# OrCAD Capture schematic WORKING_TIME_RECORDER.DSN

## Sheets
1 DOOR: size A; title: Door controler Eletronic Schematic; rev: DRC; note: 4
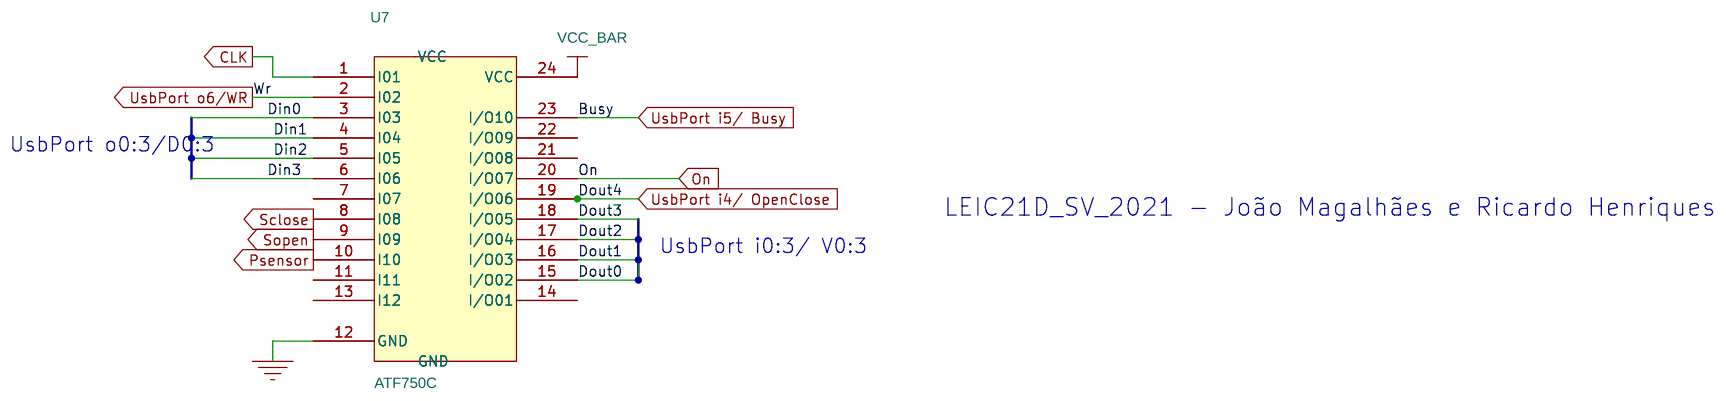
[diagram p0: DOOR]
2 LCD: size A; title: LCD Eletronic Schematic; rev: LCD; note: 3
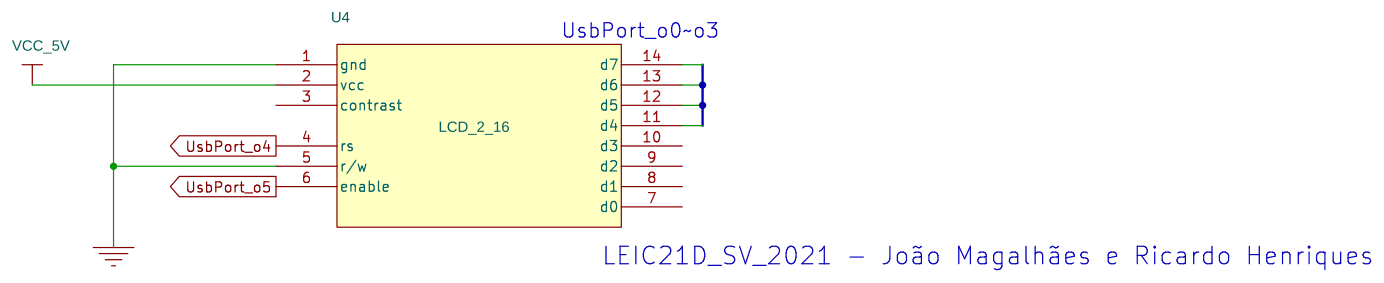
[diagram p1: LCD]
3 KeyTransmitter: size A; title: KeyBoard Transmiter Eletronic Schematic; rev: KBT; note: 2
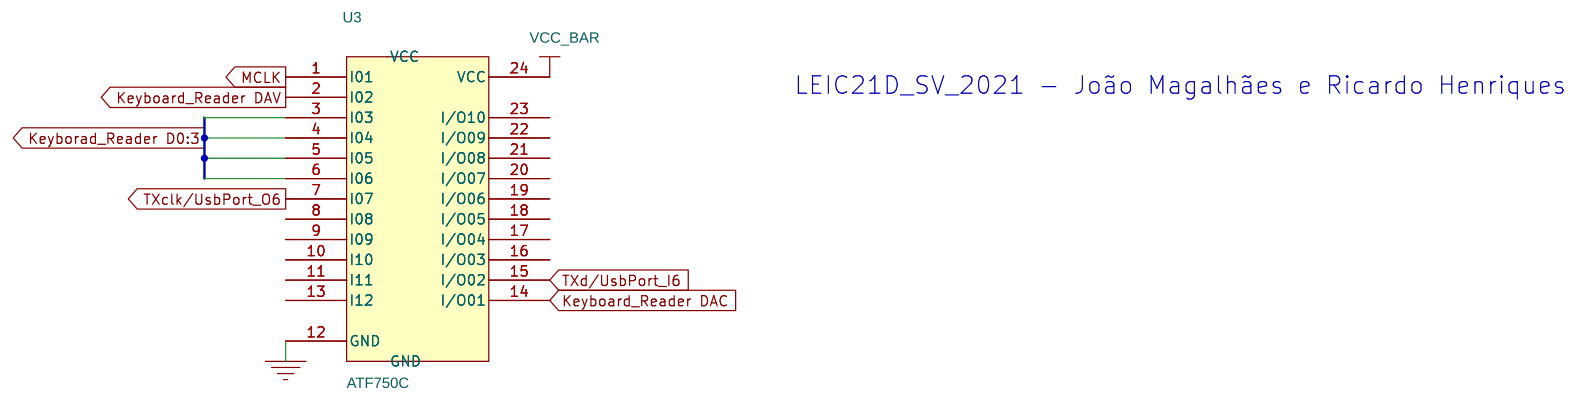
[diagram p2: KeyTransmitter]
4 Keyboard_Reader: size A; title: KeyBoard Reader Eletronic Schematic; rev: KBR; note: 1
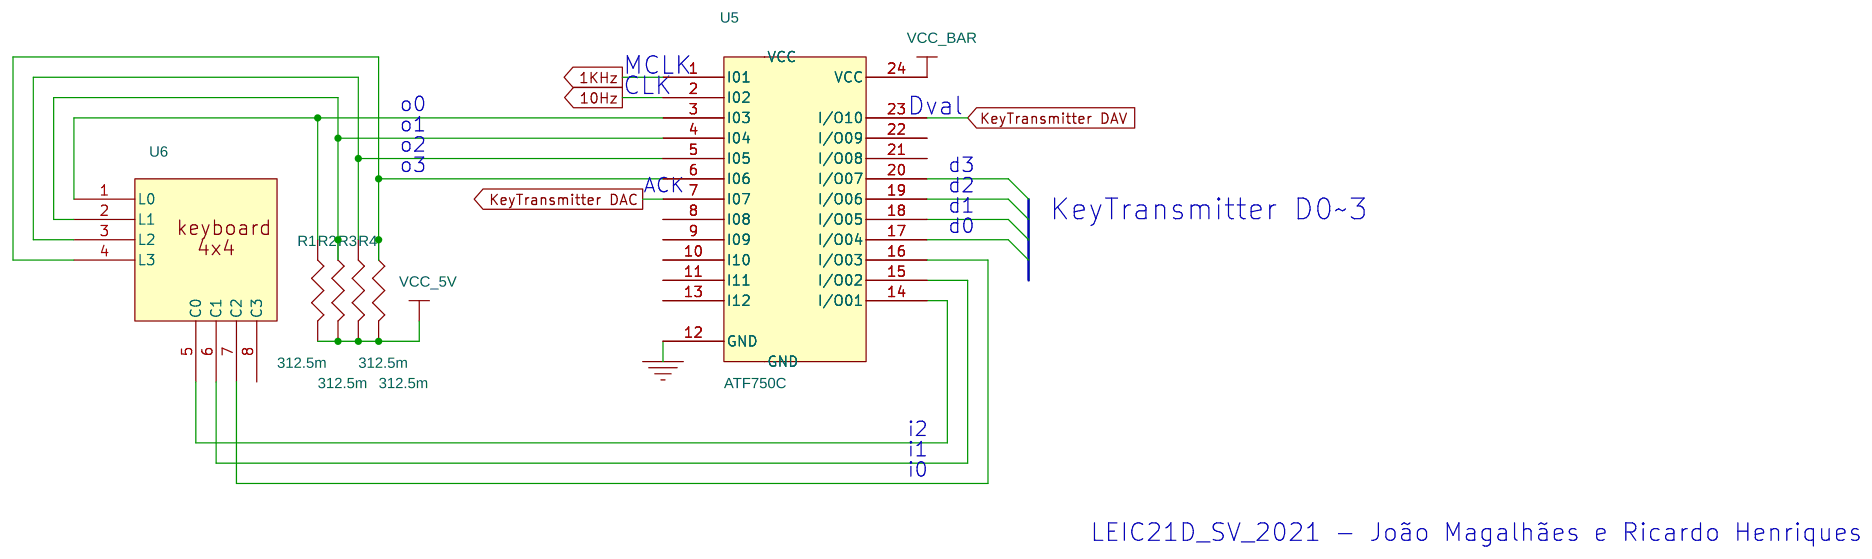
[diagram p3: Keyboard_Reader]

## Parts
sheet DOOR
U7  ATF750C
sheet Keyboard_Reader
R1  312.5m
R2  312.5m
R3  312.5m
R4  312.5m
U5  ATF750C
U6  4x4
sheet KeyTransmitter
U3  ATF750C
sheet LCD
U4  LCD_2_16

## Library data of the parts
U3 U5 U7 = ATF750C
R1-R4 = RESISTOR
U6 = 4x4Keyboard
U4 = LCD_2_16

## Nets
GND: U3.GND U4.1(gnd) U4.5(r/w) U5.12(GND) U5.GND U7.12(GND) U7.GND
GND_POWER: U3.12(GND)
VCC: U3.VCC U5.VCC U7.VCC
VCC_5V: R1.2 R2.2 R3.2 R4.2 U3.24(VCC) U4.2(vcc) U5.24(VCC) U7.24(VCC)
1KHz: U5.1(I01)
10Hz: U5.2(I02)
CLK: U7.1(I01)
Din0: U7.3(I03)
Din1: U7.4(I04)
Din2: U7.5(I05)
Din3: U7.6(I06)
Dout0: U7.15(I/O02) U7.16(I/O03)
Dout2: U7.17(I/O04)
Dout3: U7.18(I/O05)
Keyboard_Reader DAC: U3.14(I/O01)
Keyboard_Reader DAV: U3.2(I02)
Keyborad_Reader D0:3: U3.4(I04)
KeyTransmitter DAC: U5.7(I07)
KeyTransmitter DAV: U5.23(I/O10)
MCLK: U3.1(I01)
On: U7.20(I/O07)
Psensor: U7.10(I10)
Sclose: U7.8(I08)
Sopen: U7.9(I09)
TXclk/UsbPort_O6: U3.7(I07)
TXd/UsbPort_I6: U3.15(I/O02)
UsbPort i4/ OpenClose: U7.19(I/O06)
UsbPort i5/ Busy: U7.23(I/O10)
UsbPort o6/WR: U7.2(I02)
UsbPort_o4: U4.4(rs)
UsbPort_o5: U4.6(enable)
N05318: U5.14(I/O01) U6.5(C0)
N05326: U5.15(I/O02) U6.6(C1)
N05340: U5.16(I/O03) U6.7(C2)
N05398: R1.1 U5.3(I03) U6.1(L0)
N05406: R2.1 U5.4(I04) U6.2(L1)
N05418: R3.1 U5.5(I05) U6.3(L2)
N05430: R4.1 U5.6(I06) U6.4(L3)

Not connected (* = marked no-connect by the designer): U3 3(I03) 5(I05) 6(I06) 8(I08) 9(I09) 10(I10) 11(I11) 13(I12) 16(I/O03) 17(I/O04) 18(I/O05) 19(I/O06) 20(I/O07) 21(I/O08) 22(I/O09) 23(I/O10); U4 3(contrast) 7(d0) 8(d1) 9(d2) 10(d3) 11(d4) 12(d5) 13(d6) 14(d7); U5 8(I08) 9(I09) 10(I10) 11(I11) 13(I12) 17(I/O04) 18(I/O05) 19(I/O06) 20(I/O07) 21(I/O08) 22(I/O09); U6 8(C3); U7 7(I07) 11(I11) 13(I12) 14(I/O01) 21(I/O08) 22(I/O09)

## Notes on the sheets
sheet 1
- UsbPort o0:3/D0:3
- LEIC21D_SV_2021 - João Magalhães e Ricardo Henriques
- UsbPort i0:3/ V0:3
sheet 2
- UsbPort_o0~o3
- LEIC21D_SV_2021 - João Magalhães e Ricardo Henriques
sheet 3
- LEIC21D_SV_2021 - João Magalhães e Ricardo Henriques
sheet 4
- MCLK
- CLK
- o0
- Dval
- o1
- o2
- o3
- d3
- ACK
- d2
- d1
- KeyTransmitter D0~3
- d0
- i2
- i1
- i0
- LEIC21D_SV_2021 - João Magalhães e Ricardo Henriques
